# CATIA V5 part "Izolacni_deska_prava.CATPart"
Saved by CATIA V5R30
Part number: Izolacni_deska_prava
Definition: E 1400_396 446_8_90
Nomenclature: E 1400_396 446_8_90
Source: Unknown
Description: PART--DESC
Bounding box of the stored display mesh (mm): x -223 to 223, y -198 to 198, z 132.7 to 140.7
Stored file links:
  E:\Bakalarka\Model\Forma_v7\Izolacni_deska_prava.CATPart
  E:\Bakalarka\Model\Forma_v7\Vstrikovaci_cast.CATProduct
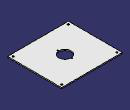
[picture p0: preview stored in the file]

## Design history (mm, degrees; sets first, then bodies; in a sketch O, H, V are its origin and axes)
Body1 "MANIFOLD_SOLID_BREP #3778" (main body)
  Solid1: solid without history
  Sketch1 on face of Solid1, origin (0, 0, 140.7), H (1, 0, 0), V (0, 1, 0)
    point P1 (203, -178)
    point P2 (203, 178)
    point P3 (-203, 178)
    point P4 (-203, -178)
    reference projected line E1 (-223, -198) -> (223, -198) from edge [face of Solid1 | face of Solid1]
    reference projected line E2 (223, -198) -> (223, 198) from edge [face of Solid1 | face of Solid1]
    reference projected line E3 (223, 198) -> (-223, 198) from edge [face of Solid1 | face of Solid1]
    reference projected line E4 (-223, 198) -> (-223, -198) from edge [face of Solid1 | face of Solid1]
    distance P1 E1 = 20
    distance P1 E2 = 20
    distance P2 E3 = 20
    distance P2 E2 = 20
    distance P3 E3 = 20
    distance P4 E1 = 20
    distance P4 E4 = 20
    distance P3 E4 = 20
  Body2 "Result of DrillHole"
    Solid2: linked copy from another document
  Assemble1 "DrillHoleLocatingRing_E1362_2.1": tool Body2
  Body3 "Result of DrillHole"
    Solid3: linked copy from another document
  Assemble2 "DrillHoleCapScrew_E1200_5.1": tool Body3
  Body4 "Result of DrillHole"
    Solid4: linked copy from another document
  Assemble3 "DrillHoleCapScrew_E1200_5.2": tool Body4
  Body5 "Result of DrillHole"
    Solid5: linked copy from another document
  Assemble4 "DrillHoleCountersunkScrew_E1220_5.1": tool Body5
  Body6 "Result of DrillHole"
    Solid6: linked copy from another document
  Assemble5 "DrillHoleCountersunkScrew_E1220_5.2": tool Body6
  Body7 "Result of DrillHole"
    Solid7: linked copy from another document
  Assemble6 "DrillHoleCountersunkScrew_E1220_5.3": tool Body7
  Body8 "Result of DrillHole"
    Solid8: linked copy from another document
  Assemble7 "DrillHoleCountersunkScrew_E1220_5.4": tool Body8
  Sketch2 on face of Solid1, origin (0, 0, 140.7), H (1, 0, 0), V (0, 1, 0)
    point P1 (0, 0)
    coincidence: P1 O
  Sketch3 on face of Solid1, origin (0, 0, 140.7), H (1, 0, 0), V (0, 1, 0)
    point P1 (192.1978, 179.5519)
    point P2 (-193.8334, 175.7673)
